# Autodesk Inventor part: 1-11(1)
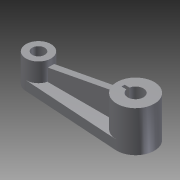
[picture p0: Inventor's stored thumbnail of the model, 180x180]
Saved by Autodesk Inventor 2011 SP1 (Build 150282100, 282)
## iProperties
Created: 2014-02
Part Number: 1-11(1)
Document SubType Name: Modeling
Designer: Administrator
Density: 1 g/cm^3
Author: Administrator
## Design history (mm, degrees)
sketch "草图1"
  geometry: L1 (-15.5, -4)-(15.111, -5.987); L2 (-15.5, 4)-(15.111, 5.987); A1 r 4 centre (-15.5, 0) between (-15.5, 4) and (-15.5, -4); A2 r 6 centre (15.5, 0) between (15.111, -5.987) and (15.111, 5.987); 2 further points
  constraints: 4 end point, 4 point on circle, 2 centre point, 2 coincident, 2 tangent
  dimensions: "d0" = 8 diameter of A1; "d1" = 12 diameter of A2
extrude "拉伸1" new body sketch "草图1" distance "d2" = 3; taper "d3" = 0 deg
sketch "草图2"
  geometry: C1 r 6 at (15.5, 0); A1 r 4 centre (-15.5, 0) between (-15.5, 4) and (-15.5, -4) reference; A2 r 6 centre (15.5, 0) between (15.111, -5.987) and (15.111, 5.987) reference; 2 further points
  constraints: 2 coincident, 1 centre point, 1 concentric, 1 vertical alignment, 2 other
extrude "拉伸2" join sketch "草图2" distance "d4" = 6; taper "d5" = 0 deg
sketch "草图3"
  geometry: C1 r 6 at (15.5, 0); A1 r 6 centre (15.5, 0) between (15.111, -5.987) and (15.111, 5.987) reference; 1 further point
  constraints: 1 centre point, 1 coincident, 1 concentric
extrude "拉伸3" join sketch "草图3" distance "d6" = 10; taper "d7" = 0 deg
sketch "草图4"
  geometry: C1 r 4 at (0, 0) reference; C2 r 2 at (0, 0); 1 further point
  constraints: 1 centre point, 1 coincident
  dimensions: "d8" = 4 diameter of C2
extrude "拉伸4" cut sketch "草图4" stored distance "d9" = 8; taper "d10" = 0 deg
sketch "草图5"
  geometry: L1 (-4, -0.5)-(-4, 0.5); L2 (-4, -0.5)-(-2.449, -0.5); L3 (-4, 0.5)-(-2.449, 0.5); C1 r 6 at (0, 0) reference; A1 r 2.5 centre (0, 0) between (-2.449, -0.5) and (-2.449, 0.5); 2 further points
  constraints: 6 end point, 2 point on circle, 1 centre point, 1 coincident, 1 horizontal alignment, 1 midpoint, 1 parallel, 1 perpendicular, 1 vertical
  dimensions: "d11" = 5 diameter of A1; "d12" = 1 distance of L1.start L1.end
extrude "拉伸5" cut sketch "草图5" stored distance "d13" = 8; taper "d14" = 0 deg
sketch "草图6"
  geometry: L1 (11.5, 3)-(11.5, 9) reference; L2 (-9.5, 3)-(-9.5, 13) reference; L3 (11.5, 7)-(-9.5, 11); L4 (15.5, 3)-(-15.111, 3) reference; 1 further point
  constraints: 2 end point, 2 point on line
extrude "拉伸6" join sketch "草图6" stored distance "d15" = 2; taper "d16" = 0 deg
node "实体1"
